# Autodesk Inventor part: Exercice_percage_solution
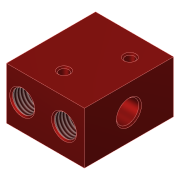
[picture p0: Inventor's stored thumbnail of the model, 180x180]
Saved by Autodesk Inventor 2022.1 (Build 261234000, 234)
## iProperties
Created: 2018-06
Part Number: Exercice_percage_solution
Material: Générique
Document SubType Name: Modeling
Designer: Fabian Perrée
Density: 1 g/cm^3
Appearance: Anodisé - Rouge
Mass: 46.4496 g
Surface Area: 130.388 cm^2
Volume: 46.4496 cm^3
Author: Fabian Perrée
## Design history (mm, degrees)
sketch "Esquisse1"
  geometry: L1 (-21, 24)-(21, 24); L2 (21, 24)-(21, -24); L3 (21, -24)-(-21, -24); L4 (-21, -24)-(-21, 24); L5 (-21, 24)-(21, -24); L6 (21, 24)-(-21, -24); 1 further point
  constraints: 12 end point, 2 midpoint, 2 parallel, 1 horizontal, 1 perpendicular
  dimensions: "d0" = 48 distance of L1.end L2.end; "d1" = 42 distance of L2.end L3.end
extrude "Extrusion1" new body sketch "Esquisse1" stored distance "d2" = 28; taper "d3" = 0 deg
sketch "Esquisse2"
  geometry: L1 (21, 24)-(21, -24) reference; L2 (21, 0)-(-21, 0); L3 (-21, 24)-(21, 24) reference; L4 (21, -24)-(-21, -24) reference; L5 (0, -24)-(0, 24); L6 (12.5, 24)-(12.5, 0); L7 (18.5, 24)-(18.5, 13); L8 (18.5, 13)-(17.75, 13); L9 (16.25, 11.5)-(16.25, 10); L10 (16.25, 10)-(14.5, 10); L11 (14.5, 10)-(14.5, 0); L12 (21, -6)-(8.5, -6); L13 (8.5, -6)-(8.5, -5.25); L14 (8.5, -5.25)-(5.5, -5.25); L15 (5.5, -5.25)-(5.5, -2.5); L16 (5.5, -2.5)-(0.5, -2.5); L17 (0.5, -2.5)-(0.5, -2); L18 (0.5, -2)-(-0.5, -2); L19 (-0.5, -2)-(-0.5, -6); L20 (-0.5, -6)-(-21, -6); L21 (-21, -24)-(-21, 24) reference; L22 (21, -6)-(21, 0); L23 (-21, -6)-(-21, 0); A1 r 1.5 centre (17.75, 11.5) between (17.75, 13) and (16.25, 11.5); 2 further points
  constraints: 38 end point, 12 perpendicular, 8 point on line, 3 horizontal, 3 midpoint, 2 point on circle, 2 tangent, 1 centre point, 1 collinear, 1 parallel, 1 vertical
  dimensions: "d6" = 12 diameter of L7 L6; "d7" = 8.5 distance between parallel lines of L1 L6; "d8" = 7.5 diameter of L9 L6; "d9" = 4 diameter of L11 L6; "d10" = 11 distance of L7.start L7.end; "d11" = 3 distance of point (16.25, 13) L9.end; "d12" = 1.5 radius of A1; "d19" = 12 diameter of L12 L2; "d20" = 10.5 diameter of L14 L2; "d21" = 5 diameter of L16 L2; "d22" = 4 diameter of L18 L2; "d23" = 1 distance of L17.end L18.end; "d24" = 12 diameter of L20 L2; "d25" = 12.5 distance of L12.start L12.end; "d26" = 15.5 distance between parallel lines of L15 L1; "d27" = 20.5 distance of L19.end L20.end
revolve "Révolution1" stored, may be unused: angle "d35" = 90 deg
sketch "Esquisse3"
  geometry: C1 r 6 at (8.5, -14) reference; 2 further points
  constraints: 1 horizontal alignment
  dimensions: "d36" = 22.5 distance of C1.centre point (31, -14)
sketch "Esquisse4"
  geometry: L1 (42, 0)-(42, -28) reference; 2 further points
  constraints: 1 horizontal alignment
  dimensions: "d37" = 18 distance from line of L1 point (24, -14)
feature "Filetage1" dims "d42" = 10, "d43" = 0
feature "Réseau basé sur une esquisse1"
feature "Réseau basé sur une esquisse2"
revolve "Révolution2" stored, may be unused: angle "d38" = 90 deg
feature "Filetage2" dims "d47" = 10, "d48" = 0
sketch "Esquisse5"
  geometry: C1 r 2.5 at (-24, 14) reference; C2 r 2 at (-24, 14) reference; 2 further points
  dimensions: "d49" = 19 horizontal distance of C1.centre point (-43, 5); "d50" = 9 vertical distance of C2.centre point (-43, 5); "d51" = 19 horizontal distance of point (-5, 23) C1.centre; "d52" = 9 vertical distance of point (-5, 23) C1.centre
hole "Perçage1" sketch "Esquisse5" at (-43, 5), (-5, 23) diameter "d53" = 4.134; stored, may be unused: countersink angle "d57" = 90 deg, drill point angle "d59" = 118 deg; dims "d54" = 10, "d55" = 4, "d56" = 2, "d58" = 12.5
sketch "Esquisse6"
  geometry: L1 (21, 24)-(-21, 24) reference; L2 (21, -24)-(21, 24) reference; L3 (-21, 24)-(-21, -24) reference; L4 (-21, -24)-(21, -24) reference; 3 further points
  dimensions: "d63" = 12 distance from line of L1 point (9.5, 12); "d65" = 19 distance from line of L3 point (-2, -12); "d66" = 12 distance from line of L4 point (-2, -12); "d74" = 30.5 distance from line of L3 point (9.5, 12)
hole "Perçage2" sketch "Esquisse6" at (9.5, 12), (-2, -12) diameter "d67" = 5; stored, may be unused: countersink angle "d71" = 90 deg, drill point angle "d73" = 118 deg; dims "d68" = 10, "d69" = 4, "d70" = 2, "d72" = 12.5
chamfer "Chanfrein4" distance "d75" = 0.75; stored, may be unused: second distance "d76" = 2, angle "d77" = 45 deg
feature "Scission1"
node "Solide1"
